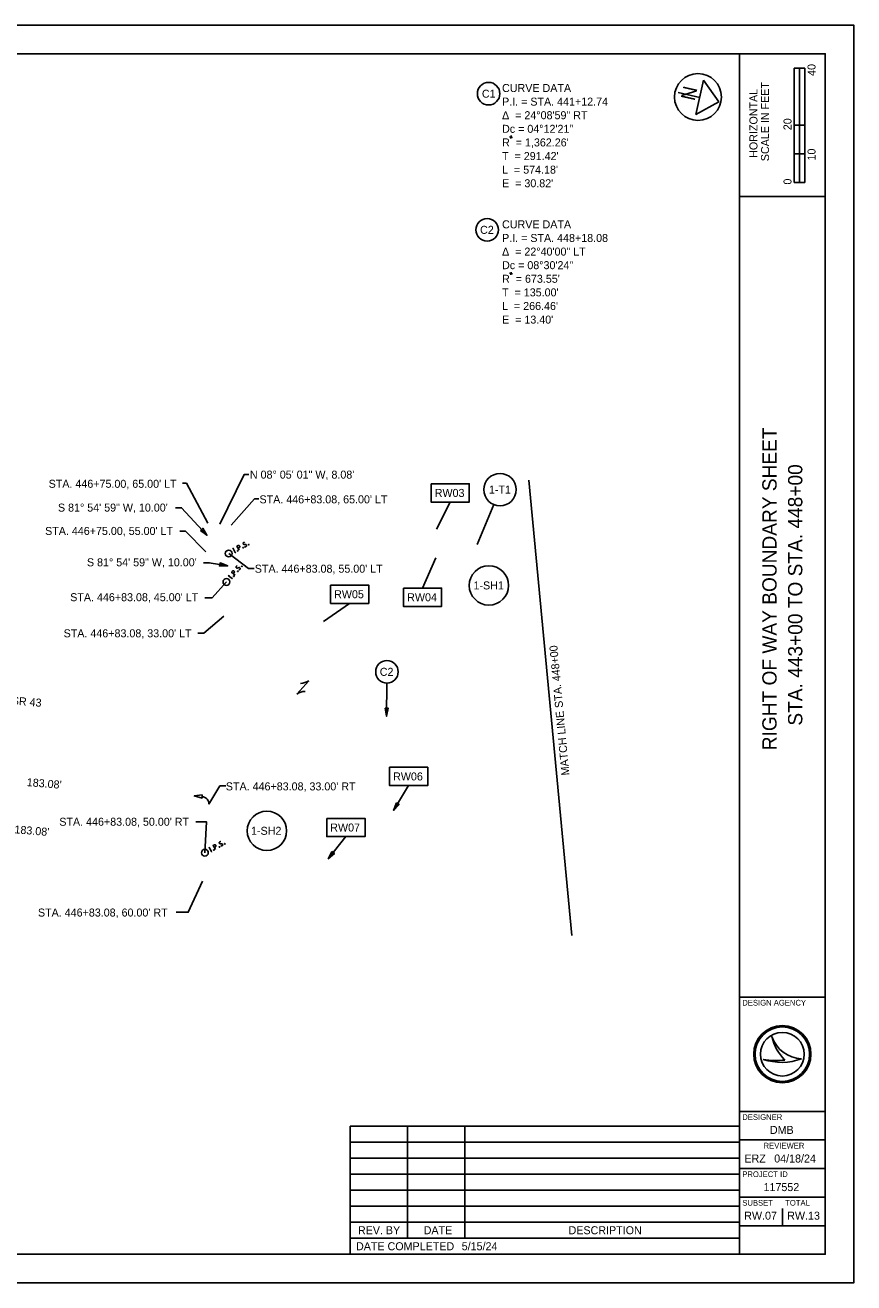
# Model space of a CAD drawing. Extents: x -36 to 740, y -224 to 440.
# Drawn here: x 390.2 to 680, y 0 to 440 of the extents above; entities that cross this region are included whole.
import ezdxf

# ---------------------------------------------------------------- set-up
doc = ezdxf.new("R2010")
doc.units = 0
for name, color, linetype in [('_CIVIL_CONSTRUCTION', 7, 'Continuous'), ('CM_Corridor_Final', 7, 'Continuous'), ('CM_Corridor_Range_Final', 7, 'Continuous'), ('MD_P_ACB_B', 7, 'Continuous'), ('MD_P_ACB_T', 7, 'Continuous'), ('MD_P_ACIC_B', 7, 'Continuous'), ('MD_P_ACSC_B', 7, 'Continuous'), ('MD_P_ACSC_T', 7, 'Continuous'), ('PV_P_EOP', 7, 'Continuous')]:
    doc.layers.add(name, color=color, linetype=linetype)

msp = doc.modelspace()

# ---------------------------------------------------------------- linework, layer by layer
at = {"layer": '_CIVIL_CONSTRUCTION'}
msp.add_lwpolyline([(0, 0), (680, 0), (680, 440), (0, 440)], close=True, dxfattribs=at)
at = {"layer": 'CM_Corridor_Final'}
for p, q in [((659.13, 385), (659.13, 425)), ((662.88, 425), (659.13, 425)), ((659.13, 405), (659.13, 425)), ((659.13, 425), (661, 425)), ((661, 425), (661.02, 425)), ((661.02, 425), (661.02, 405)), ((662.88, 425), (662.88, 385)), ((661.02, 405), (659.13, 405)), ((662.87, 405), (661, 405)), ((661, 405), (661, 395)), ((662.87, 395), (662.87, 405)), ((661, 395), (659.13, 395)), ((659.13, 395), (659.13, 385)), ((661, 385), (661, 395)), ((661, 395), (662.87, 395)), ((662.88, 385), (659.13, 385)), ((659.13, 385), (661, 385)), ((566.31, 280.82), (581.34, 121.53)), ((566.31, 280.82), (581.34, 121.53)), ((651.35, 86.19), (651.35, 86.19)), ((655, 80), (655, 80)), ((648.34, 78.19), (648.34, 78.19)), ((661.75, 78.37), (661.75, 78.37)), ((655, 20), (655, 26))]:
    msp.add_line(p, q, dxfattribs=at)
for radius in [10, 9.54, 9.54, 7.64]:
    msp.add_circle((655, 80), radius, dxfattribs=at)
for centre, radius, start, end in [((662.32, 89.95), 11.6, 198.9257, 198.9319), ((666.93, 89.4), 15.91, 191.6379, 191.6421), ((662.32, 89.95), 11.6, 198.9319, 267.1657), ((666.93, 89.4), 15.91, 191.6421, 226.0947), ((654.79, 97.4), 20.26, 251.4576, 290.0832), ((652.96, 103.09), 25.32, 259.4964, 259.4995), ((654.79, 97.4), 20.26, 251.4527, 251.4576), ((652.96, 103.09), 25.32, 259.4995, 276.6672)]:
    msp.add_arc(centre, radius, start, end, dxfattribs=at)
at = {"layer": 'CM_Corridor_Range_Final'}
for p, q in [((640, 10), (640, 430)), ((640, 380), (670, 380)), ((640, 100), (670, 100)), ((640, 60), (670, 60)), ((640, 50), (670, 50)), ((640, 40), (670, 40)), ((640, 30), (670, 30)), ((640, 20), (670, 20))]:
    msp.add_line(p, q, dxfattribs=at)
msp.add_lwpolyline([(30, 430), (670, 430), (670, 10), (30, 10)], close=True, dxfattribs=at)
at = {"layer": 'MD_P_ACB_B'}
msp.add_circle((625.5, 414.86), 8.2, dxfattribs=at)
msp.add_circle((625.5, 414.86), 8.2, dxfattribs=at)
at = {"layer": 'MD_P_ACB_T'}
for p, q in [((560.61, 400.74), (559.63, 400.96)), ((560.23, 401.34), (560.01, 400.36)), ((560.12, 400.85), (560.12, 400.85)), ((560.61, 353.04), (559.63, 353.26)), ((560.23, 353.64), (560.01, 352.66)), ((560.12, 353.15), (560.12, 353.15))]:
    msp.add_line(p, q, dxfattribs=at)
at = {"layer": 'MD_P_ACIC_B'}
for p, q in [((627.48, 420.72), (624.79, 408.71)), ((627.48, 420.72), (624.79, 408.71)), ((632.8, 413.22), (627.48, 420.72)), ((632.8, 413.22), (627.48, 420.72)), ((626.14, 414.71), (618.59, 416.41)), ((626.14, 414.71), (618.59, 416.41)), ((624.79, 408.71), (632.8, 413.22)), ((624.79, 408.71), (632.8, 413.22)), ((538.86, 273.14), (534.08, 263.66)), ((554.11, 272.3), (548.27, 258.27)), ((529.19, 243.05), (533.87, 253.64)), ((503.7, 237.7), (494.52, 231.4)), ((516.72, 209.82), (516.64, 198.23)), ((524.32, 173.97), (519.07, 165.25)), ((502.4, 156.1), (496.21, 148.34)), ((503.93, 54.8), (503.93, 10)), ((503.93, 54.8), (640, 54.8)), ((523.93, 54.8), (523.93, 15.6)), ((543.93, 54.8), (543.93, 15.6)), ((503.93, 49.2), (640, 49.2)), ((503.93, 43.6), (640, 43.6)), ((503.93, 38), (640, 38)), ((503.93, 32.4), (640, 32.4)), ((503.93, 26.8), (640, 26.8)), ((503.93, 21.2), (640, 21.2)), ((503.93, 15.6), (640, 15.6)), ((640, 10), (640, 10))]:
    msp.add_line(p, q, dxfattribs=at)
for points in [[(468.48, 282.85), (466.86, 282.84), (458.32, 265.43)], [(445.31, 279.72), (446.62, 279.72), (454.16, 265.77)], [(462.22, 265.12), (470.46, 274.3), (471.92, 274.3)], [(442.81, 271.18), (444.95, 271.18), (453.82, 261.53)], [(444.36, 263.03), (446.25, 263.03), (453.37, 255.8)], [(452.62, 251.92), (454.61, 251.92), (461.08, 250.84)], [(470.37, 249.87), (468.35, 249.87), (461.42, 255.16)], [(453.07, 239.67), (455.65, 239.69), (460.63, 245.19)], [(450.58, 227.34), (452.76, 227.34), (459.67, 233.23)], [(460.42, 173.83), (458.32, 173.83), (454.43, 167.43)], [(449.91, 161.26), (453.67, 161.26), (453.08, 150.49)], [(443.07, 129.69), (447.24, 129.65), (452.29, 140.52)]]:
    msp.add_lwpolyline(points, dxfattribs=at)
for points in [[(532.18, 279.55), (545.54, 279.55), (545.54, 273.14), (532.18, 273.14)], [(451.52, 263.21), (452.34, 263.97), (453.82, 261.53)], [(458.22, 250.75), (458.41, 251.85), (461.08, 250.84)], [(497.02, 244.11), (510.38, 244.11), (510.38, 237.7), (497.02, 237.7)], [(522.51, 243.05), (535.87, 243.05), (535.87, 236.64), (522.51, 236.64)], [(516.1, 201.03), (517.22, 201.02), (516.64, 198.23)], [(517.64, 180.38), (531, 180.38), (531, 173.97), (517.64, 173.97)], [(452.18, 170.68), (452.09, 169.57), (449.35, 170.35)], [(520.04, 167.94), (521, 167.36), (519.07, 165.25)], [(495.72, 162.5), (509.08, 162.5), (509.08, 156.1), (495.72, 156.1)], [(497.52, 150.88), (498.39, 150.18), (496.21, 148.34)]]:
    msp.add_lwpolyline(points, close=True, dxfattribs=at)
for centre, radius in [((625.5, 414.86), 8.2), ((625.5, 414.86), 8.2), ((552.3, 416.02), 3.94), ((551.82, 368.39), 3.94), ((556.28, 277.51), 5.65), ((552.4, 243.99), 6.88), ((516.75, 213.76), 3.94), ((474.78, 158.15), 6.88)]:
    msp.add_circle(centre, radius, dxfattribs=at)
msp.add_arc((451.94, 167.63), 2.5, 355.4436, 85.4436, dxfattribs=at)
at = {"layer": 'MD_P_ACSC_B'}
for points in [[(462.79, 256.84), (463.1, 257.01)], [(463.73, 255.53), (462.95, 256.93)], [(463.57, 255.44), (463.88, 255.61)], [(465.09, 256.29), (464.31, 257.69), (464.78, 257.95), (464.83, 257.96), (464.91, 257.98), (464.95, 257.97), (464.99, 257.97), (465.06, 257.93), (465.12, 257.89), (465.19, 257.82), (465.26, 257.68), (465.28, 257.64), (465.3, 257.56), (465.3, 257.46), (465.28, 257.41), (465.26, 257.37), (465.23, 257.32), (465.16, 257.26), (464.69, 257.01)], [(464.46, 256.18), (464.51, 256.21), (464.55, 256.2), (464.6, 256.18), (464.63, 256.12), (464.63, 256.06), (464.61, 256.02), (464.56, 256), (464.52, 256), (464.47, 256.03), (464.44, 256.09), (464.44, 256.15), (464.46, 256.18)], [(467, 259.06), (466.96, 259.07), (466.92, 259.07), (466.82, 259.06), (466.7, 259.02), (466.62, 258.98), (466.59, 258.96), (466.49, 258.86), (466.42, 258.73), (466.4, 258.61), (466.43, 258.51), (466.47, 258.44), (466.54, 258.37), (466.66, 258.33), (467.37, 258.3), (467.44, 258.28), (467.49, 258.25), (467.54, 258.19), (467.58, 258.13), (467.61, 258.06), (467.62, 258.01), (467.63, 257.94), (467.64, 257.89), (467.64, 257.84), (467.63, 257.79), (467.61, 257.75), (467.58, 257.71), (467.56, 257.68), (467.48, 257.62), (467.35, 257.55), (467.25, 257.52), (467.08, 257.53), (466.96, 257.55)], [(466.42, 257.28), (466.47, 257.31), (466.51, 257.3), (466.57, 257.27), (466.6, 257.22), (466.59, 257.16), (466.58, 257.12), (466.53, 257.09), (466.49, 257.1), (466.43, 257.13), (466.4, 257.18), (466.41, 257.24), (466.42, 257.28)], [(468.33, 258.34), (468.38, 258.37), (468.42, 258.36), (468.47, 258.34), (468.5, 258.28), (468.5, 258.22), (468.48, 258.18), (468.43, 258.16), (468.39, 258.16), (468.34, 258.19), (468.31, 258.25), (468.31, 258.31), (468.33, 258.34)], [(464.4, 250.85), (464.37, 250.85), (464.32, 250.84), (464.23, 250.79), (464.14, 250.71), (464.08, 250.64), (464.06, 250.62), (464, 250.48), (463.98, 250.34), (464.01, 250.22), (464.07, 250.14), (464.13, 250.09), (464.22, 250.04), (464.35, 250.05), (465.02, 250.28), (465.1, 250.29), (465.15, 250.28), (465.22, 250.24), (465.28, 250.2), (465.33, 250.14), (465.36, 250.1), (465.4, 250.04), (465.42, 249.99), (465.44, 249.95), (465.45, 249.9), (465.44, 249.86), (465.44, 249.81), (465.42, 249.78), (465.37, 249.69), (465.27, 249.57), (465.19, 249.51), (465.03, 249.46), (464.92, 249.44)], [(461.29, 247.26), (461.52, 247.53)], [(462.64, 246.37), (461.4, 247.39)], [(463.63, 247.58), (462.4, 248.6), (462.73, 249.01), (462.78, 249.04), (462.85, 249.09), (462.89, 249.1), (462.93, 249.11), (463.01, 249.1), (463.08, 249.08), (463.17, 249.04), (463.28, 248.94), (463.32, 248.9), (463.36, 248.84), (463.4, 248.75), (463.4, 248.69), (463.4, 248.65), (463.38, 248.59), (463.34, 248.51), (463, 248.1)], [(462.53, 246.24), (462.75, 246.51)], [(463.08, 247.25), (463.12, 247.29), (463.16, 247.3), (463.22, 247.3), (463.27, 247.26), (463.28, 247.2), (463.28, 247.16), (463.25, 247.11), (463.21, 247.11), (463.15, 247.11), (463.1, 247.15), (463.08, 247.21), (463.08, 247.25)], [(464.51, 248.99), (464.55, 249.03), (464.59, 249.04), (464.65, 249.03), (464.7, 248.99), (464.71, 248.93), (464.71, 248.89), (464.68, 248.85), (464.64, 248.84), (464.58, 248.85), (464.53, 248.89), (464.51, 248.95), (464.51, 248.99)], [(465.9, 250.67), (465.93, 250.71), (465.97, 250.72), (466.03, 250.72), (466.08, 250.68), (466.1, 250.62), (466.1, 250.58), (466.06, 250.54), (466.02, 250.53), (465.96, 250.53), (465.92, 250.57), (465.9, 250.63), (465.9, 250.67)], [(458.67, 154.36), (458.64, 154.38), (458.6, 154.38), (458.49, 154.37), (458.38, 154.33), (458.3, 154.29), (458.27, 154.27), (458.16, 154.17), (458.09, 154.04), (458.07, 153.92), (458.1, 153.82), (458.14, 153.75), (458.21, 153.68), (458.33, 153.64), (459.04, 153.6), (459.11, 153.59), (459.16, 153.55), (459.21, 153.5), (459.25, 153.43), (459.28, 153.36), (459.29, 153.31), (459.3, 153.25), (459.31, 153.19), (459.31, 153.15), (459.3, 153.1), (459.28, 153.06), (459.25, 153.02), (459.23, 152.99), (459.15, 152.93), (459.01, 152.86), (458.92, 152.83), (458.75, 152.84), (458.63, 152.86)], [(454.46, 152.17), (454.77, 152.34)], [(455.39, 150.85), (454.61, 152.25)], [(455.23, 150.77), (455.54, 150.94)], [(456.76, 151.61), (455.98, 153.01), (456.45, 153.26), (456.5, 153.28), (456.58, 153.3), (456.62, 153.29), (456.66, 153.28), (456.73, 153.25), (456.79, 153.21), (456.86, 153.13), (456.93, 153), (456.95, 152.95), (456.96, 152.87), (456.97, 152.78), (456.95, 152.72), (456.93, 152.68), (456.9, 152.63), (456.82, 152.58), (456.36, 152.32)], [(456.12, 151.5), (456.17, 151.53), (456.21, 151.52), (456.27, 151.49), (456.3, 151.44), (456.29, 151.38), (456.27, 151.34), (456.23, 151.31), (456.19, 151.32), (456.13, 151.35), (456.1, 151.4), (456.11, 151.46), (456.12, 151.5)], [(458.09, 152.59), (458.14, 152.62), (458.18, 152.61), (458.23, 152.58), (458.26, 152.53), (458.26, 152.47), (458.24, 152.43), (458.19, 152.4), (458.15, 152.41), (458.1, 152.44), (458.07, 152.49), (458.07, 152.55), (458.09, 152.59)], [(460, 153.65), (460.05, 153.67), (460.09, 153.67), (460.14, 153.64), (460.17, 153.58), (460.17, 153.52), (460.15, 153.49), (460.1, 153.46), (460.06, 153.46), (460.01, 153.49), (459.98, 153.55), (459.98, 153.61), (460, 153.65)]]:
    msp.add_lwpolyline(points, dxfattribs=at)
for centre in [(461.42, 255.16), (460.63, 245.19), (453.08, 150.49)]:
    msp.add_circle(centre, 1.2, dxfattribs=at)
at = {"layer": 'PV_P_EOP'}
for p, q in [((485.29, 205.96), (489.4, 210.67)), ((487.34, 208.31), (487.34, 208.31))]:
    msp.add_line(p, q, dxfattribs=at)
for centre, start, end in [((488.35, 201.59), 92.3403, 124.9828), ((486.34, 215.04), 272.3403, 304.9828)]:
    msp.add_arc(centre, 5.34, start, end, dxfattribs=at)

# ---------------------------------------------------------------- texts
at = {"layer": 'CM_Corridor_Final'}
for s, height, rotation, p in [('40', 2.8, 90, (666.61, 422.25)), ('SCALE IN FEET', 2.8, 90, (650.35, 392.41)), ('HORIZONTAL', 2.8, 90, (646.3, 393.58)), ('20', 2.8, 90, (658.21, 403.25)), ('10', 2.8, 90, (666.61, 392.65)), ('0', 2.8, 90, (658.21, 384.23)), ('RIGHT OF WAY BOUNDARY SHEET', 5, 90, (653, 186.33)), ('STA. 443+00 TO STA. 448+00', 5, 90, (662, 194.94)), ('MATCH LINE STA. 448+00', 2.8, 95.3895, (580.59, 177.66))]:
    msp.add_text(s, height=height, rotation=rotation, dxfattribs=at).set_placement(p)
for s, height, p in [('DESIGN AGENCY', 2, (641, 97)), ('DESIGNER', 2, (641, 57)), ('DMB', 2.8, (650.65, 52.1)), ('REVIEWER', 2, (648.44, 47)), ('ERZ', 2.8, (641.74, 42.1)), ('04/18/24', 2.8, (652.16, 42.1)), ('PROJECT ID', 2, (641, 37)), ('117552', 2.8, (648.42, 32.1)), ('SUBSET', 2, (641, 27)), ('TOTAL', 2, (656, 27)), ('RW.07', 2.8, (641.67, 22.1)), ('RW.13', 2.8, (656.7, 22.1))]:
    msp.add_text(s, height=height, dxfattribs=at).set_placement(p)
at = {"layer": 'MD_P_ACIC_B'}
for s, height, rotation, p in [('N', 5, 257.36, (620.48, 419.08)), ('N', 5, 257.36, (620.48, 419.08)), (' of R/W SR 43', 2.8, 355.4436, (372, 203.42)), ("183.08'", 2.8, 355.4436, (390.73, 173.8)), ("183.08'", 2.8, 355.4436, (386.42, 157.29))]:
    msp.add_text(s, height=height, rotation=rotation, dxfattribs=at).set_placement(p)
for s, p in [('C1', (549.95, 414.62)), ('C2', (549.31, 366.99)), ('N 08° 05\' 01" W, 8.08\'', (468.82, 281.36)), ("STA. 446+75.00, 65.00' LT", (398.45, 278.15)), ('RW03', (533.46, 274.95)), ('1-T1', (552.41, 276.11)), ("STA. 446+83.08, 65.00' LT", (472.18, 272.71)), ('S 81° 54\' 59" W, 10.00\'', (401.71, 269.82)), ("STA. 446+75.00, 55.00' LT", (397.21, 261.65)), ('S 81° 54\' 59" W, 10.00\'', (411.84, 250.68)), ("STA. 446+83.08, 55.00' LT", (470.53, 248.44)), ('RW05', (498.27, 239.51)), ('1-SH1', (547.01, 242.59)), ("STA. 446+83.08, 45.00' LT", (405.99, 238.47)), ('RW04', (523.82, 238.45)), ("STA. 446+83.08, 33.00' LT", (403.69, 225.84)), ('C2', (514.24, 212.36)), ('RW06', (518.9, 175.77)), ("STA. 446+83.08, 33.00' RT", (460.41, 172.28)), ("STA. 446+83.08, 50.00' RT", (402.18, 159.91)), ('1-SH2', (469.22, 156.75)), ('RW07', (496.92, 157.9)), ("STA. 446+83.08, 60.00' RT", (394.71, 128.15)), ('REV. BY', (506.61, 17)), ('DATE', (529.59, 17)), ('DESCRIPTION', (580.25, 17)), ('DATE COMPLETED', (505.93, 11.4)), ('5/15/24                            ', (542.89, 11.4))]:
    msp.add_text(s, height=2.8, dxfattribs=at).set_placement(p)
at = {"layer": 'MD_P_ACSC_T'}
for s, p in [('CURVE DATA', (557, 416.61)), ('CURVE DATA', (557, 416.61)), ('P.I. = STA. 441+12.74', (557, 411.85)), ('P.I. = STA. 441+12.74', (557, 411.85)), ('Δ  = 24°08\'59" RT', (557, 407.09)), ('Δ  = 24°08\'59" RT', (557, 407.09)), ('Dc = 04°12\'21"', (557, 402.33)), ('Dc = 04°12\'21"', (557, 402.33)), ("R  = 1,362.26'", (557, 397.57)), ("R  = 1,362.26'", (557, 397.57)), ("T  = 291.42'", (557, 392.81)), ("T  = 291.42'", (557, 392.81)), ("L  = 574.18'", (557, 388.05)), ("L  = 574.18'", (557, 388.05)), ("E  = 30.82'", (557, 383.29)), ("E  = 30.82'", (557, 383.29)), ('CURVE DATA', (557, 368.91)), ('CURVE DATA', (557, 368.91)), ('P.I. = STA. 448+18.08', (557, 364.15)), ('P.I. = STA. 448+18.08', (557, 364.15)), ('Δ  = 22°40\'00" LT', (557, 359.39)), ('Δ  = 22°40\'00" LT', (557, 359.39)), ('Dc = 08°30\'24"', (557, 354.63)), ('Dc = 08°30\'24"', (557, 354.63)), ("R  = 673.55'", (557, 349.87)), ("R  = 673.55'", (557, 349.87)), ("T  = 135.00'", (557, 345.11)), ("T  = 135.00'", (557, 345.11)), ("L  = 266.46'", (557, 340.35)), ("L  = 266.46'", (557, 340.35)), ("E  = 13.40'", (557, 335.59)), ("E  = 13.40'", (557, 335.59))]:
    msp.add_text(s, height=2.8, dxfattribs=at).set_placement(p)

doc.saveas('drawing.dxf')
